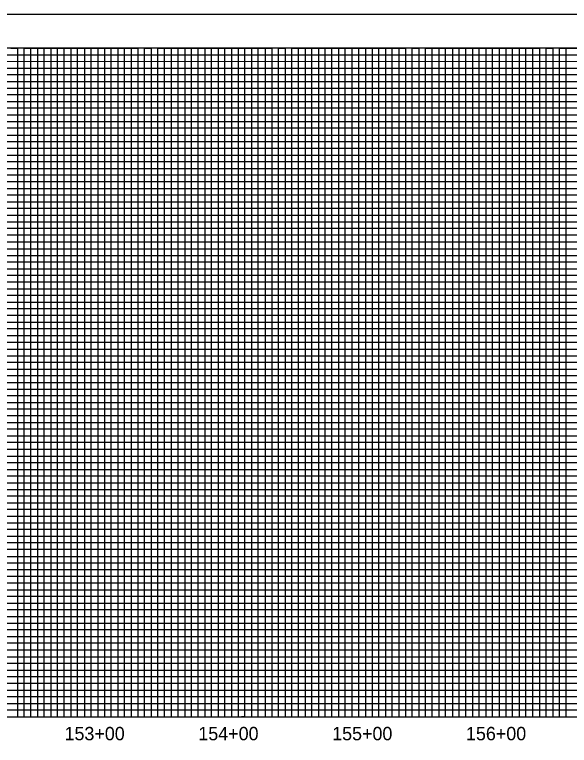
# Model space of a CAD drawing. Extents: x 505602 to 507286, y 483109 to 484209.
# Drawn here: x 506457 to 506872, y 483662 to 484209 of the extents above; entities that cross this region are included whole.
import ezdxf

# ---------------------------------------------------------------- set-up
doc = ezdxf.new("R2010")
doc.units = 0
for name, color, linetype in [('Exist Vertical Profile Vertical Axis Label', 7, 'Continuous'), ('Scratch_Level_4', 7, 'Continuous'), ('Sheet Layout Profile Border Port 1', 7, 'Continuous'), ('Sheet Plot Border Outside CELL', 7, 'Continuous'), ('Sheet Profile CELL', 7, 'Continuous'), ('Sheet Profile Grid Major CELL', 7, 'Continuous'), ('Sheet Profile Grid Middle CELL', 7, 'Continuous'), ('Sheet Profile Grid Minor CELL', 7, 'Continuous')]:
    doc.layers.add(name, color=color, linetype=linetype)

msp = doc.modelspace()

# ---------------------------------------------------------------- linework, layer by layer
at = {"layer": 'Scratch_Level_4'}
msp.add_lwpolyline([(507269.08, 483683.71), (507269.07, 484022.66), (507069.03, 484022.66), (507069.03, 484142), (507016.54, 484142), (507016.54, 484183.71), (505818.69, 484183.71), (505818.69, 483683.71)], close=True, dxfattribs=at)
at = {"layer": 'Sheet Layout Profile Border Port 1'}
msp.add_lwpolyline([(505819.08, 484183.71), (505819.08, 483683.71), (507069.08, 483683.71), (507269.07, 484022.66), (507269.07, 484022.66), (507069.08, 484183.71)], close=True, dxfattribs=at)
at = {"layer": 'Sheet Plot Border Outside CELL'}
msp.add_lwpolyline([(505602.08, 483108.71), (507286.08, 483108.71), (507286.08, 484208.71), (505602.08, 484208.71)], close=True, dxfattribs=at)
at = {"layer": 'Sheet Profile CELL'}
msp.add_line((505769.08, 483683.71), (507269.08, 483683.71), dxfattribs=at)
msp.add_lwpolyline([(507269.08, 484183.71), (505769.08, 484183.71), (505769.08, 483133.71), (507269.08, 483133.71)], close=True, dxfattribs=at)
at = {"layer": 'Sheet Profile Grid Major CELL'}
for points in [[(506419.08, 483683.71), (506469.08, 483683.71), (506469.08, 484183.71), (506519.08, 484183.71), (506519.08, 483683.71), (506569.08, 483683.71), (506569.08, 484183.71), (506619.08, 484183.71), (506619.08, 483683.71), (506669.08, 483683.71), (506669.08, 484183.71), (506719.08, 484183.71), (506719.08, 483683.71), (506769.08, 483683.71), (506769.08, 484183.71), (506819.08, 484183.71), (506819.08, 483683.71), (506869.08, 483683.71), (506869.08, 484183.71), (506919.08, 484183.71)], [(505769.08, 484133.71), (507069.08, 484133.71)], [(507069.08, 484083.71), (505769.08, 484083.71), (505769.08, 484033.71), (507069.08, 484033.71)], [(507269.08, 483983.71), (505769.08, 483983.71), (505769.08, 483933.71), (507269.08, 483933.71)], [(507269.08, 483883.71), (505769.08, 483883.71), (505769.08, 483833.71), (507269.08, 483833.71)], [(507269.08, 483783.71), (505769.08, 483783.71), (505769.08, 483783.71), (505769.08, 483733.71), (507269.08, 483733.71)]]:
    msp.add_lwpolyline(points, dxfattribs=at)
at = {"layer": 'Sheet Profile Grid Middle CELL'}
msp.add_line((505769.08, 484158.71), (507069.03, 484158.71), dxfattribs=at)
for points in [[(506444.08, 483683.71), (506494.08, 483683.71), (506494.08, 484183.71), (506544.08, 484183.71), (506544.08, 483683.71), (506594.08, 483683.71), (506594.08, 484183.71), (506644.08, 484183.71), (506644.08, 483683.71), (506694.08, 483683.71), (506694.08, 484183.71), (506744.08, 484183.71), (506744.08, 483683.71), (506794.08, 483683.71), (506794.08, 484183.71), (506844.08, 484183.71), (506844.08, 483683.71), (506894.08, 483683.71)], [(507069.08, 484108.71), (505769.08, 484108.71), (505769.08, 484058.71), (507069.08, 484058.71)], [(507269.08, 484008.71), (505769.08, 484008.71), (505769.08, 483958.71), (507094.08, 483958.71)], [(507269.08, 483908.71), (505769.08, 483908.71), (505769.08, 483858.71), (507269.08, 483858.71)], [(507269.08, 483808.71), (505769.08, 483808.71), (505769.08, 483758.71), (507269.08, 483758.71)], [(507269.08, 483708.71), (505769.08, 483708.71)]]:
    msp.add_lwpolyline(points, dxfattribs=at)
at = {"layer": 'Sheet Profile Grid Minor CELL'}
for p, q in [((505819.08, 484178.71), (507069.08, 484178.71)), ((507069.08, 484173.71), (505819.08, 484173.36)), ((505819.08, 484168.71), (507069.08, 484168.71)), ((507069.03, 484048.71), (505819.08, 484048.71)), ((507069.08, 484043.71), (505819.08, 484043.71)), ((507069.08, 484038.71), (505819.08, 484038.71)), ((505819.08, 484028.71), (507069.08, 484028.71)), ((507069.08, 484023.71), (505819.08, 484023.71)), ((505819.08, 484018.71), (507219.08, 484018.71)), ((507219.08, 483998.71), (505819.08, 483998.71)), ((505819.08, 483993.71), (507219.08, 483993.71)), ((507219.08, 483973.71), (505819.08, 483973.71)), ((505819.08, 483968.71), (507219.08, 483968.71)), ((507219.08, 483948.71), (505819.08, 483948.71)), ((505819.08, 483943.71), (507219.08, 483943.71)), ((507219.08, 483938.71), (505819.08, 483938.71)), ((505819.08, 483928.71), (507219.08, 483928.71)), ((507219.08, 483923.71), (505819.08, 483923.71)), ((505819.08, 483918.71), (507219.08, 483918.71)), ((507219.08, 483913.71), (505819.08, 483913.71)), ((505819.08, 483903.71), (507219.08, 483903.71)), ((507219.08, 483898.71), (505819.08, 483898.71)), ((505819.08, 483893.71), (507219.08, 483893.71)), ((507219.08, 483888.71), (505819.08, 483888.71)), ((505819.08, 483878.71), (507219.08, 483878.71)), ((507219.08, 483873.71), (505819.08, 483873.71)), ((505819.08, 483868.71), (507219.08, 483868.71)), ((507219.08, 483863.71), (505819.08, 483863.71)), ((505819.08, 483853.71), (507219.08, 483853.71)), ((507219.08, 483848.71), (505819.08, 483848.71)), ((505819.08, 483843.71), (507219.08, 483843.71)), ((507219.08, 483838.71), (505819.08, 483838.71)), ((505819.08, 483828.71), (507219.08, 483828.71)), ((507219.08, 483823.71), (505819.08, 483823.71)), ((505819.08, 483818.71), (507219.08, 483818.71)), ((507219.08, 483813.71), (505819.08, 483813.71)), ((505819.08, 483803.71), (507219.08, 483803.71)), ((507219.08, 483798.71), (505819.08, 483798.71)), ((507219.08, 483793.71), (505819.08, 483793.71)), ((507219.08, 483788.71), (505819.08, 483788.71)), ((505819.08, 483778.71), (507219.08, 483778.71)), ((507219.08, 483773.71), (505819.08, 483773.71)), ((505819.08, 483768.71), (507219.08, 483768.71)), ((507219.08, 483763.71), (505819.08, 483763.71)), ((505819.08, 483753.71), (507219.08, 483753.71)), ((507219.08, 483748.71), (505819.08, 483748.71)), ((505819.08, 483743.71), (507219.08, 483743.71)), ((507219.08, 483738.71), (505819.08, 483738.71)), ((505819.08, 483728.71), (507219.08, 483728.71)), ((507219.08, 483723.71), (505819.08, 483723.71)), ((505819.08, 483718.71), (507219.08, 483718.71)), ((507219.08, 483713.71), (505819.08, 483713.71)), ((505819.08, 483703.71), (507219.08, 483703.71)), ((507219.08, 483698.71), (505819.08, 483698.71)), ((505819.08, 483693.71), (507219.08, 483693.71))]:
    msp.add_line(p, q, dxfattribs=at)
for points in [[(506454.08, 484183.71), (506459.08, 484183.71), (506459.08, 483683.71), (506464.08, 483683.71), (506464.08, 484183.71), (506474.08, 484183.71), (506474.08, 483683.71), (506474.08, 483683.71), (506479.08, 483683.71), (506479.08, 484183.71), (506484.08, 484183.71), (506484.08, 483683.71), (506489.08, 483683.71), (506489.08, 484183.71), (506499.08, 484183.71), (506499.08, 483683.71), (506504.08, 483683.71), (506504.08, 484183.71), (506509.08, 484183.71), (506509.08, 483683.71), (506514.08, 483683.71), (506514.08, 484183.71), (506524.08, 484183.71), (506524.08, 483683.71), (506529.08, 483683.71), (506529.08, 484183.71), (506534.08, 484183.71), (506534.08, 483683.71), (506539.08, 483683.71), (506539.08, 484183.71), (506549.08, 484183.71), (506549.08, 483683.71), (506554.08, 483683.71), (506554.08, 484183.71), (506559.08, 484183.71), (506559.08, 483683.71), (506564.08, 483683.71), (506564.08, 484183.71), (506574.08, 484183.71), (506574.08, 483683.71), (506579.08, 483683.71), (506579.08, 484183.71), (506584.08, 484183.71), (506584.08, 483683.71), (506589.08, 483683.71), (506589.08, 484183.71), (506599.08, 484183.71), (506599.08, 483683.71), (506604.08, 483683.71), (506604.08, 484183.71), (506609.08, 484183.71), (506609.08, 483683.71), (506614.08, 483683.71), (506614.08, 484183.71), (506624.08, 484183.71), (506624.08, 483683.71), (506628.78, 483684.26), (506629.08, 483683.71), (506629.08, 484183.71), (506634.08, 484183.71), (506634.08, 483683.71), (506639.08, 483683.71), (506639.08, 484183.71), (506649.08, 484183.71), (506649.08, 483683.71), (506654.08, 483683.71)], [(506654.08, 483683.71), (506654.08, 484183.71), (506659.08, 484183.71), (506659.08, 483683.71), (506664.08, 483683.71), (506664.08, 484183.71), (506674.08, 484183.71), (506674.08, 483683.71), (506679.08, 483683.71), (506679.08, 484183.71), (506684.08, 484183.71), (506684.08, 483683.71), (506689.08, 483683.71), (506689.08, 484183.71), (506699.08, 484183.71), (506699.08, 483683.71), (506704.08, 483683.71), (506704.08, 484183.71), (506709.08, 484183.71), (506709.08, 483683.71), (506714.08, 483683.71), (506714.08, 484183.71), (506724.08, 484183.71), (506724.08, 483683.71), (506729.08, 483683.71), (506729.08, 484183.71), (506734.08, 484183.71), (506734.08, 483683.71), (506739.08, 483683.71), (506739.08, 484183.71), (506749.08, 484183.71), (506749.08, 483683.71), (506754.08, 483683.71), (506754.08, 484183.71), (506759.08, 484183.71), (506759.08, 483683.71), (506764.08, 483683.71), (506764.08, 484183.71), (506774.08, 484183.71), (506774.08, 483683.71), (506779.08, 483683.71), (506779.08, 484183.71), (506784.08, 484183.71), (506784.08, 483683.71), (506789.08, 483683.71), (506789.08, 484183.71), (506799.08, 484183.71), (506799.08, 483683.71), (506804.08, 483683.71), (506804.08, 484183.71), (506809.08, 484183.71), (506809.08, 483683.71), (506814.08, 483683.71), (506814.08, 484183.71), (506824.08, 484183.71), (506824.08, 483683.71), (506829.08, 483683.71), (506829.08, 484183.71), (506834.08, 484183.71), (506834.08, 483683.71), (506839.08, 483683.71), (506839.08, 484183.71), (506849.08, 484183.71), (506849.08, 483683.71), (506854.08, 483683.71), (506854.08, 484183.71), (506859.08, 484183.71), (506859.08, 483683.71), (506864.08, 483683.71), (506864.08, 484183.71), (506874.08, 484183.71)], [(507069.08, 484163.71), (505819.08, 484163.71), (505819.08, 484153.71), (507069.08, 484153.71)], [(507069.03, 484148.71), (505819.08, 484148.71), (505819.08, 484143.71), (507069.08, 484143.71)], [(507069.08, 484138.71), (505819.08, 484138.71), (505819.08, 484128.71), (507069.08, 484128.71)], [(507069.08, 484123.71), (505819.08, 484123.71), (505819.08, 484118.71), (507069.08, 484118.71)], [(507069.08, 484113.71), (505819.08, 484113.71), (505819.08, 484103.71), (507069.08, 484103.71)], [(507069.08, 484098.71), (505819.08, 484098.71), (505819.08, 484093.71), (507069.08, 484093.71)], [(507069.08, 484088.71), (505819.08, 484088.71), (505819.08, 484078.71), (507069.08, 484078.71)], [(507069.08, 484073.61), (505819.18, 484073.61), (505819.18, 484068.71), (507069.08, 484068.71)], [(507069.08, 484063.71), (505819.08, 484063.71), (505819.08, 484053.71), (507069.08, 484053.71)], [(507219.08, 484013.71), (505819.08, 484013.71), (505819.08, 484003.71), (507219.08, 484003.71)], [(507219.08, 483988.71), (505819.08, 483988.71), (505819.08, 483978.71), (507219.08, 483978.71)], [(507219.08, 483963.71), (505819.08, 483963.71), (505819.08, 483953.71), (507219.08, 483953.71)], [(507219.08, 483688.71), (505819.08, 483688.71)]]:
    msp.add_lwpolyline(points, dxfattribs=at)

# ---------------------------------------------------------------- texts
at = {"layer": 'Exist Vertical Profile Vertical Axis Label'}
for s, p in [('153+00', (506494.26, 483666.21)), ('154+00', (506594.26, 483666.21)), ('155+00', (506694.26, 483666.21)), ('156+00', (506794.26, 483666.21))]:
    msp.add_text(s, height=10, dxfattribs=at).set_placement(p)

doc.saveas('drawing.dxf')
